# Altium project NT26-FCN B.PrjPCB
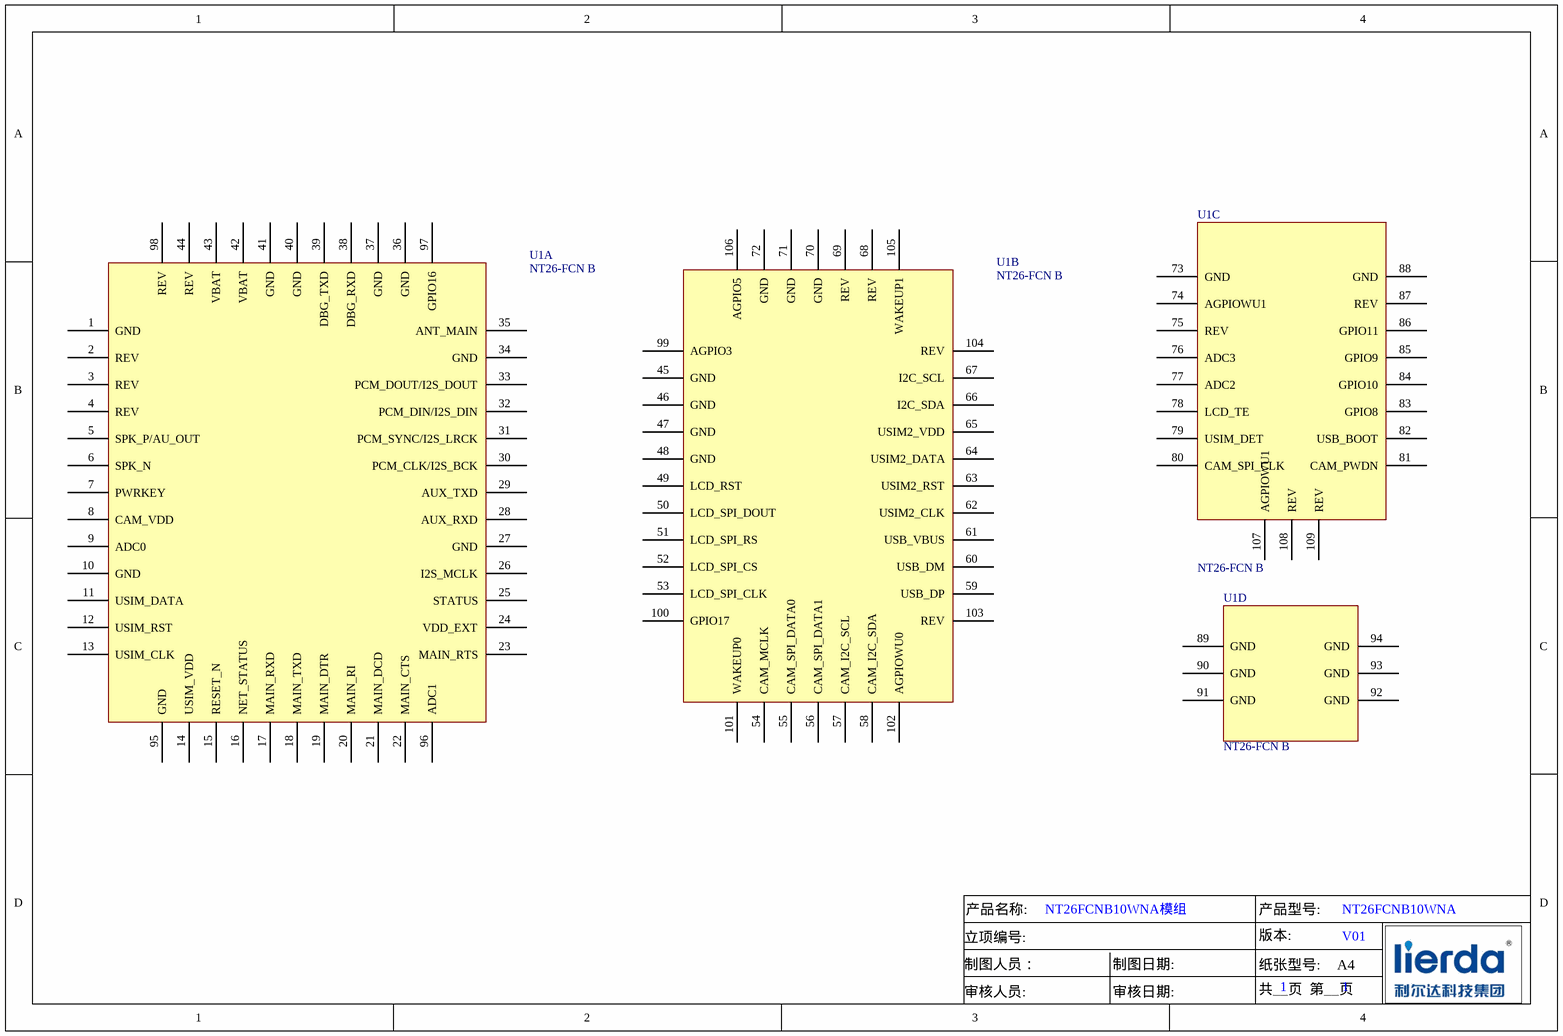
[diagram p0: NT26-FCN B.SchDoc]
1 sheet, 1 parts. Net scope: global (net labels, ports and power ports of the same name join across sheets).
Board file: NT26-FCN B.PcbDoc

## Sheet NT26-FCN B.SchDoc
size A4; Organization: Altium Limited; Address1: L3, 12a Rodborough Rd; Address2: Frenchs Forest; Address3: NSW; Address4: Australia 2086

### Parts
U1  NT26-FCN B  [NT26-FCN B]  (parts A,B,C,D of 4)

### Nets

Not connected (* = marked no-connect by the designer): U1 1(GND) 2(REV) 3(REV) 4(REV) 5(SPK_P/AU_OUT) 6(SPK_N) 7(PWRKEY) 8(CAM_VDD) 9(ADC0) 10(GND) 11(USIM_DATA) 12(USIM_RST) 13(USIM_CLK) 14(USIM_VDD) 15(RESET_N) 16(NET_STATUS) 17(MAIN_RXD) 18(MAIN_TXD) 19(MAIN_DTR) 20(MAIN_RI) 21(MAIN_DCD) 22(MAIN_CTS) 23(MAIN_RTS) 24(VDD_EXT) 25(STATUS) 26(I2S_MCLK) 27(GND) 28(AUX_RXD) 29(AUX_TXD) 30(PCM_CLK/I2S_BCK) 31(PCM_SYNC/I2S_LRCK) 32(PCM_DIN/I2S_DIN) 33(PCM_DOUT/I2S_DOUT) 34(GND) 35(ANT_MAIN) 36(GND) 37(GND) 38(DBG_RXD) 39(DBG_TXD) 40(GND) 41(GND) 42(VBAT) 43(VBAT) 44(REV) 45(GND) 46(GND) 47(GND) 48(GND) 49(LCD_RST) 50(LCD_SPI_DOUT) 51(LCD_SPI_RS) 52(LCD_SPI_CS) 53(LCD_SPI_CLK) 54(CAM_MCLK) 55(CAM_SPI_DATA0) 56(CAM_SPI_DATA1) 57(CAM_I2C_SCL) 58(CAM_I2C_SDA) 59(USB_DP) 60(USB_DM) 61(USB_VBUS) 62(USIM2_CLK) 63(USIM2_RST) 64(USIM2_DATA) 65(USIM2_VDD) 66(I2C_SDA) 67(I2C_SCL) 68(REV) 69(REV) 70(GND) 71(GND) 72(GND) 73(GND) 74(AGPIOWU1) 75(REV) 76(ADC3) 77(ADC2) 78(LCD_TE) 79(USIM_DET) 80(CAM_SPI_CLK) 81(CAM_PWDN) 82(USB_BOOT) 83(GPIO8) 84(GPIO10) 85(GPIO9) 86(GPIO11) 87(REV) 88(GND) 89(GND) 90(GND) 91(GND) 92(GND) 93(GND) 94(GND) 95(GND) 96(ADC1) 97(GPIO16) 98(REV) 99(AGPIO3) 100(GPIO17) 101(WAKEUP0) 102(AGPIOWU0) 103(REV) 104(REV) 105(WAKEUP1) 106(AGPIO5) 107(AGPIOWU1) 108(REV) 109(REV)

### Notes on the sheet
- 产品名称:
- NT26FCNB10WNA模组
- 产品型号:
- NT26FCNB10WNA
- 制图人员：
- 立项编号:
- 制图日期:
- 版本:
- 纸张型号:
- 1
- A4
- V01
- 审核人员:
- 审核日期:
- 共__页  第__页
